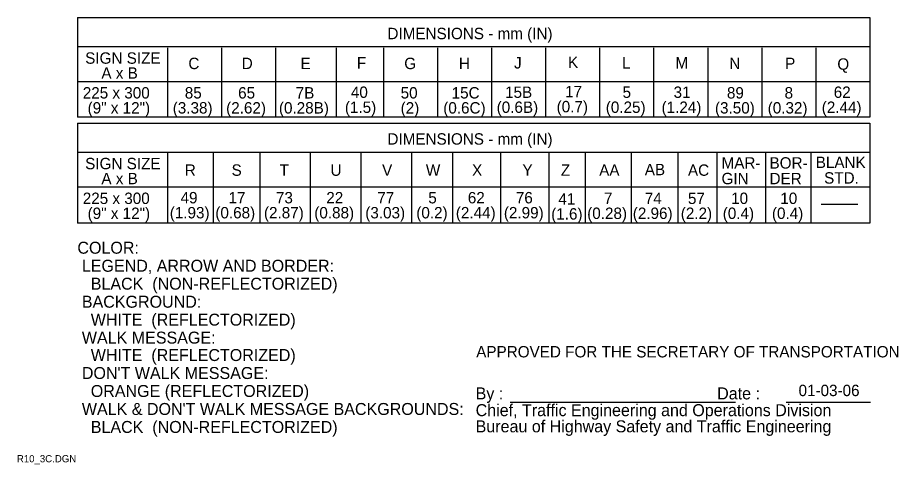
# Model space of a CAD drawing. Extents: x 0.013 to 0.196, y 0.004 to 0.259.
# Drawn here: x 0.0128 to 0.1964, y 0.0039 to 0.0971 of the extents above; entities that cross this region are included whole.
import ezdxf

# ---------------------------------------------------------------- set-up
doc = ezdxf.new("R2010")
doc.units = 0
for name, color, linetype in [('1', 7, 'Continuous'), ('3', 7, 'Continuous'), ('4', 7, 'Continuous')]:
    doc.layers.add(name, color=color, linetype=linetype)

msp = doc.modelspace()

# ---------------------------------------------------------------- linework, layer by layer
at = {"layer": '1'}
for p, q in [((0.11544, 0.01695), (0.16242, 0.01695)), ((0.17295, 0.01695), (0.19056, 0.01695))]:
    msp.add_line(p, q, dxfattribs=at)
at = {"layer": '3'}
for p, q in [((0.02525, 0.09713), (0.02525, 0.07637)), ((0.02525, 0.09713), (0.19038, 0.09713)), ((0.19038, 0.09713), (0.19038, 0.07637)), ((0.19038, 0.091), (0.02525, 0.091)), ((0.04402, 0.09083), (0.04402, 0.07631)), ((0.05528, 0.09083), (0.05528, 0.07631)), ((0.06654, 0.09083), (0.06654, 0.07631)), ((0.07921, 0.09083), (0.07921, 0.07631)), ((0.08905, 0.09083), (0.08905, 0.07631)), ((0.10031, 0.09083), (0.10031, 0.07631)), ((0.11157, 0.09083), (0.11157, 0.07631)), ((0.12283, 0.09083), (0.12283, 0.07631)), ((0.13409, 0.09083), (0.13409, 0.07631)), ((0.14535, 0.09083), (0.14535, 0.07631)), ((0.15661, 0.09083), (0.15661, 0.07631)), ((0.16787, 0.09083), (0.16787, 0.07631)), ((0.17913, 0.09083), (0.17913, 0.07631)), ((0.19038, 0.08375), (0.02525, 0.08375)), ((0.19038, 0.07637), (0.02525, 0.07637)), ((0.02525, 0.07512), (0.02525, 0.05425)), ((0.02525, 0.07512), (0.19038, 0.07512)), ((0.19038, 0.07512), (0.19038, 0.05425)), ((0.19038, 0.069), (0.02525, 0.069)), ((0.04402, 0.06894), (0.04402, 0.05419)), ((0.05353, 0.06894), (0.05353, 0.05419)), ((0.06325, 0.06894), (0.06325, 0.05419)), ((0.07379, 0.06894), (0.07379, 0.05419)), ((0.08434, 0.06894), (0.08434, 0.05419)), ((0.09488, 0.06894), (0.09488, 0.05419)), ((0.10343, 0.06894), (0.10343, 0.05419)), ((0.1134, 0.06894), (0.1134, 0.05419)), ((0.12352, 0.06894), (0.12352, 0.05419)), ((0.13106, 0.06894), (0.13106, 0.05419)), ((0.14066, 0.06894), (0.14066, 0.05419)), ((0.1504, 0.06894), (0.1504, 0.05419)), ((0.15853, 0.06891), (0.15853, 0.05428)), ((0.16868, 0.06891), (0.16868, 0.05428)), ((0.1781, 0.06891), (0.1781, 0.05428)), ((0.19038, 0.06175), (0.02525, 0.06175)), ((0.18788, 0.05813), (0.18025, 0.05813)), ((0.19038, 0.05425), (0.02525, 0.05425))]:
    msp.add_line(p, q, dxfattribs=at)

# ---------------------------------------------------------------- texts
at = {"layer": '1'}
for s, height, p in [('COLOR:', 0.0025, (0.02525, 0.04788)), (' LEGEND, ARROW AND BORDER:', 0.0024998, (0.02525, 0.04412)), ('   BLACK  (NON-REFLECTORIZED)', 0.0024998, (0.02525, 0.04038)), (' BACKGROUND:', 0.0024998, (0.02525, 0.03662)), ('   WHITE  (REFLECTORIZED)', 0.0024998, (0.02525, 0.03288)), (' WALK MESSAGE:', 0.0024998, (0.02525, 0.02913)), ('   WHITE  (REFLECTORIZED)', 0.0024998, (0.02525, 0.0255)), ('APPROVED FOR THE SECRETARY OF TRANSPORTATION', 0.0023752, (0.10837, 0.02625)), (" DON'T WALK MESSAGE:", 0.0024998, (0.02525, 0.02175)), ('   ORANGE (REFLECTORIZED)', 0.0024998, (0.02525, 0.018)), ('By :                                                Date :', 0.0024998, (0.10825, 0.0175)), (" WALK & DON'T WALK MESSAGE BACKGROUNDS:", 0.0024998, (0.02525, 0.01425)), ('Chief, Traffic Engineering and Operations Division', 0.0024998, (0.10825, 0.014)), ('   BLACK  (NON-REFLECTORIZED)', 0.0024998, (0.02525, 0.0105)), ('Bureau of Highway Safety and Traffic Engineering', 0.0024998, (0.10825, 0.01063)), ('R10_3C.DGN', 0.0015, (0.01263, 0.00438))]:
    msp.add_text(s, height=height, dxfattribs=at).set_placement(p)
at = {"layer": '3'}
for s, height, p in [('DIMENSIONS - mm (IN)', 0.0023752, (0.08987, 0.09262)), ('SIGN SIZE', 0.002375, (0.02687, 0.0875)), ('C', 0.00238, (0.04838, 0.08638)), ('D', 0.00238, (0.0595, 0.08638)), ('E', 0.00238, (0.07175, 0.08638)), ('F', 0.00238, (0.0835, 0.0865)), ('G', 0.00238, (0.09337, 0.08638)), ('H', 0.00238, (0.10475, 0.08638)), ('J', 0.00238, (0.11625, 0.0865)), ('K', 0.00238, (0.1275, 0.08663)), ('L', 0.00238, (0.13875, 0.0865)), ('M', 0.00238, (0.14988, 0.0865)), ('N', 0.00238, (0.16112, 0.08638)), ('P', 0.00238, (0.17275, 0.08638)), ('Q', 0.00238, (0.18363, 0.08625)), ('A x B', 0.002375, (0.03025, 0.08438)), ('225 x 300', 0.002375, (0.02637, 0.08025)), ('85', 0.002375, (0.04763, 0.08025)), ('65', 0.002375, (0.05875, 0.08025)), ('7B', 0.002375, (0.07075, 0.08025)), ('40', 0.002375, (0.08225, 0.08038)), ('50', 0.002375, (0.09262, 0.08025)), ('15C', 0.002375, (0.10325, 0.08025)), ('15B', 0.002375, (0.11438, 0.08038)), ('17', 0.002375, (0.12688, 0.0805)), ('5', 0.00238, (0.13887, 0.08038)), ('31', 0.002375, (0.1495, 0.08038)), ('89', 0.002375, (0.16062, 0.08025)), ('8', 0.00238, (0.17263, 0.08025)), ('62', 0.002375, (0.18288, 0.08038)), ('(9" x 12")', 0.002375, (0.02738, 0.07712)), ('(3.38)', 0.002375, (0.04512, 0.07712)), ('(2.62)', 0.002375, (0.05625, 0.07712)), ('(0.28B)', 0.002375, (0.06725, 0.07712)), ('(1.5)', 0.002375, (0.081, 0.07725)), ('(2)', 0.002375, (0.09262, 0.07712)), ('(0.6C)', 0.002375, (0.1015, 0.07712)), ('(0.6B)', 0.002375, (0.11263, 0.07725)), ('(0.7)', 0.002375, (0.12513, 0.07737)), ('(0.25)', 0.002375, (0.13537, 0.07725)), ('(1.24)', 0.002375, (0.147, 0.07725)), ('(3.50)', 0.002375, (0.15813, 0.07712)), ('(0.32)', 0.002375, (0.16912, 0.07712)), ('(2.44)', 0.002375, (0.18038, 0.07725)), ('DIMENSIONS - mm (IN)', 0.0023752, (0.08987, 0.07063)), ('MAR-', 0.002375, (0.1595, 0.06563)), ('BOR-', 0.002375, (0.1695, 0.06563)), ('BLANK', 0.002375, (0.17913, 0.06575)), ('SIGN SIZE', 0.002375, (0.02687, 0.0655)), ('R', 0.00238, (0.04763, 0.06413)), ('S', 0.00238, (0.05738, 0.06413)), ('T', 0.00238, (0.06738, 0.06413)), ('U', 0.00238, (0.078, 0.06413)), ('V', 0.00238, (0.08875, 0.06413)), ('W', 0.00238, (0.09788, 0.06413)), ('X', 0.00238, (0.1075, 0.06413)), ('Y', 0.00238, (0.118, 0.06413)), ('Z', 0.00238, (0.126, 0.06413)), ('AA', 0.002375, (0.134, 0.06413)), ('AB', 0.002375, (0.1435, 0.06425)), ('AC', 0.002375, (0.1525, 0.06413)), ('A x B', 0.002375, (0.03025, 0.06237)), ('GIN', 0.002375, (0.1595, 0.06237)), ('DER', 0.002375, (0.1695, 0.06237)), ('STD.', 0.002375, (0.18088, 0.0625)), ('225 x 300', 0.002375, (0.02637, 0.05825)), ('49', 0.002375, (0.04675, 0.05838)), ('17', 0.002375, (0.05675, 0.05838)), ('73', 0.002375, (0.06663, 0.05838)), ('22', 0.002375, (0.07712, 0.05838)), ('77', 0.002375, (0.08775, 0.05838)), ('5', 0.00238, (0.09838, 0.05838)), ('62', 0.002375, (0.10662, 0.05838)), ('76', 0.002375, (0.11663, 0.05838)), ('7', 0.00238, (0.135, 0.05825)), ('74', 0.002375, (0.1435, 0.05825)), ('57', 0.002375, (0.1525, 0.05825)), ('10', 0.002375, (0.1615, 0.05825)), ('10', 0.002375, (0.17175, 0.05825)), ('41', 0.002375, (0.1255, 0.05813)), ('(9" x 12")', 0.002375, (0.02738, 0.05513)), ('(1.93)', 0.002375, (0.0445, 0.05525)), ('(0.68)', 0.002375, (0.054, 0.05525)), ('(2.87)', 0.002375, (0.06413, 0.05525)), ('(0.88)', 0.002375, (0.07462, 0.05525)), ('(3.03)', 0.002375, (0.08525, 0.05525)), ('(0.2)', 0.002375, (0.09588, 0.05525)), ('(2.44)', 0.002375, (0.10412, 0.05525)), ('(2.99)', 0.002375, (0.11413, 0.05525)), ('(1.6)', 0.002375, (0.124, 0.055)), ('(0.28)', 0.002375, (0.1315, 0.05513)), ('(2.96)', 0.002375, (0.141, 0.05513)), ('(2.2)', 0.002375, (0.151, 0.05513)), ('(0.4)', 0.002375, (0.15975, 0.05513)), ('(0.4)', 0.002375, (0.17, 0.05513))]:
    msp.add_text(s, height=height, dxfattribs=at).set_placement(p)
at = {"layer": '4'}
msp.add_text('01-03-06', height=0.002375, dxfattribs=at).set_placement((0.17555, 0.01818))

doc.saveas('drawing.dxf')
